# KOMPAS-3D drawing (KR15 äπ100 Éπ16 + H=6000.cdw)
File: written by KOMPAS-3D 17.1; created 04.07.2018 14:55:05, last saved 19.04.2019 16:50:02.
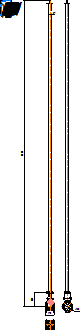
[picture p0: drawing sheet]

Sheet 1: A4, portrait

Title block, sheet 1: name: KR15 Ду100 Ру16 + H=6000; material: Внимание! Данный продукт является объектом авторского права ООО «Торговый Дом АДЛ». / Запрещается изменение, копирование, распространение / (в том числе путем копирования на другие сайты и ресурсы в Интернете) / или любое иное использование информации и объектов без предварительного / согласия правообладателя (ООО «Торговый Дом АДЛ»).; mass: 36,7; sheets: 1; organisation: ООО "Торговый дом АДЛ"; sheet format: A4; stored path: \\adlc.lan\data\АДЛ_ПКД\3D-модели\ADL production\Клиновые задвижки серии KR ГРАНАР\Клиновые задвижки KR15 со стационарным удлинением\KOMPAS 2D\KR15 Ду100 Ру16 + H=6000.cdw

Views: Проекционный вид 6, Спереди 9, Проекционный вид 10, Проекционный вид 11
Referenced files in C:\Users\kka\KOMPAS_Work\Удлинения БИВАЛ ф. ADL\!Задвижки\У_ду_40-100\: Сборка40-100.a3d
Referenced files in C:\Users\kka\KOMPAS_Work\!Trash\ГРАНАР KR Задвижки с приводами и удлинениями\С приводами\: KR15 Ду100 Ру16.m3d
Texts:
  kka
  adl
  Удлинитель штока Ду 20-100
  Крепежное изделие ГОСТ
  Болт
  ГОСТ
  Гайка
  Лит-Масса-Масштаб
  Материал-Предприятие
  Title Specification
  Body Specification ( left align )
  Body Specificaton ( centered )
  Поз.
  Кол.
  Приме-
  чание
  Таблица спецификации
Dimensions and other numbers on the sheet: 6000; 282; 190; 57; 180; 4; 1; 58; 40Х; 019; 1:1; 36,7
